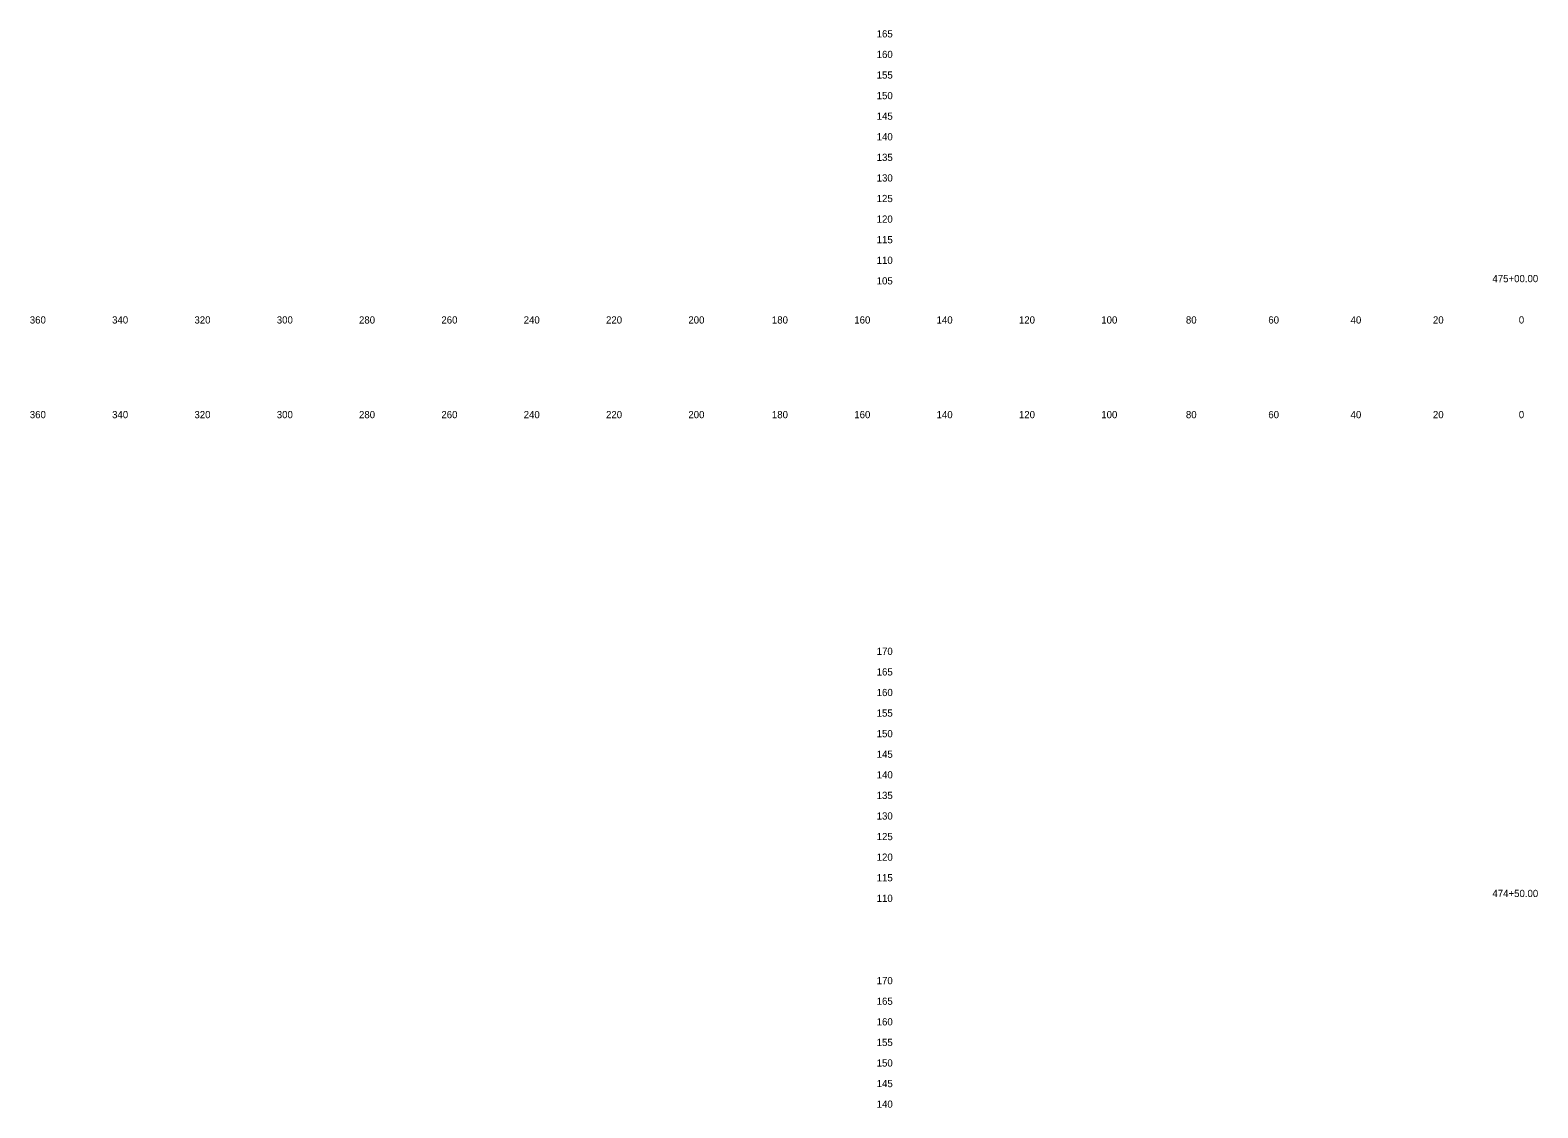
# Model space of a CAD drawing. Extents: x 21281 to 22024, y 6472 to 15198.
# Drawn here: x 21280.5 to 21646.7, y 11114.8 to 11376.6 of the extents above; entities that cross this region are included whole.
import ezdxf

# ---------------------------------------------------------------- set-up
doc = ezdxf.new("R2010")
doc.units = 0
for name, color, linetype in [('Draft_XS_Grid', 7, 'Continuous'), ('Draft_XS_Text', 7, 'Continuous'), ('SLOPE_STAKES_FILL', 7, 'Continuous')]:
    doc.layers.add(name, color=color, linetype=linetype)

msp = doc.modelspace()

# ---------------------------------------------------------------- texts
at = {"layer": 'Draft_XS_Grid'}
for s, p in [('  165  ', (21484.84, 11374.84)), ('  160  ', (21484.84, 11369.84)), ('  155  ', (21484.84, 11364.84)), ('  150  ', (21484.84, 11359.84)), ('  145  ', (21484.84, 11354.84)), ('  140  ', (21484.84, 11349.84)), ('  135  ', (21484.84, 11344.84)), ('  130  ', (21484.84, 11339.84)), ('  125  ', (21484.84, 11334.84)), ('  120  ', (21484.84, 11329.84)), ('  115  ', (21484.84, 11324.84)), ('  110  ', (21484.84, 11319.84)), ('  105  ', (21484.84, 11314.84)), ('  170  ', (21484.84, 11224.84)), ('  165  ', (21484.84, 11219.84)), ('  160  ', (21484.84, 11214.84)), ('  155  ', (21484.84, 11209.84)), ('  150  ', (21484.84, 11204.84)), ('  145  ', (21484.84, 11199.84)), ('  140  ', (21484.84, 11194.84)), ('  135  ', (21484.84, 11189.84)), ('  130  ', (21484.84, 11184.84)), ('  125  ', (21484.84, 11179.84)), ('  120  ', (21484.84, 11174.84)), ('  115  ', (21484.84, 11169.84)), ('  110  ', (21484.84, 11164.84)), ('  170  ', (21484.84, 11144.84)), ('  165  ', (21484.84, 11139.84)), ('  160  ', (21484.84, 11134.84)), ('  155  ', (21484.84, 11129.84)), ('  150  ', (21484.84, 11124.84)), ('  145  ', (21484.84, 11119.84)), ('  140  ', (21484.84, 11114.84))]:
    msp.add_text(s, height=1.75, dxfattribs=at).set_placement(p)
at = {"layer": 'Draft_XS_Text'}
for s, p in [('  360  ', (21279.14, 11305.34)), ('  340  ', (21299.13, 11305.34)), ('  320  ', (21319.13, 11305.34)), ('  300  ', (21339.13, 11305.34)), ('  280  ', (21359.1, 11305.34)), ('  260  ', (21379.11, 11305.34)), ('  240  ', (21399.1, 11305.34)), ('  220  ', (21419.1, 11305.34)), ('  200  ', (21439.1, 11305.34)), ('  180  ', (21459.39, 11305.34)), ('  160  ', (21479.4, 11305.34)), ('  140  ', (21499.39, 11305.34)), ('  120  ', (21519.39, 11305.34)), ('  100  ', (21539.39, 11305.34)), ('  80  ', (21559.95, 11305.34)), ('  60  ', (21579.97, 11305.34)), ('  40  ', (21599.95, 11305.34)), ('  20  ', (21619.95, 11305.34)), ('  0  ', (21640.81, 11305.34)), ('  0  ', (21640.81, 11305.34)), ('  360  ', (21279.14, 11282.34)), ('  340  ', (21299.13, 11282.34)), ('  320  ', (21319.13, 11282.34)), ('  300  ', (21339.13, 11282.34)), ('  280  ', (21359.1, 11282.34)), ('  260  ', (21379.11, 11282.34)), ('  240  ', (21399.1, 11282.34)), ('  220  ', (21419.1, 11282.34)), ('  200  ', (21439.1, 11282.34)), ('  180  ', (21459.39, 11282.34)), ('  160  ', (21479.4, 11282.34)), ('  140  ', (21499.39, 11282.34)), ('  120  ', (21519.39, 11282.34)), ('  100  ', (21539.39, 11282.34)), ('  80  ', (21559.95, 11282.34)), ('  60  ', (21579.97, 11282.34)), ('  40  ', (21599.95, 11282.34)), ('  20  ', (21619.95, 11282.34)), ('  0  ', (21640.81, 11282.34)), ('  0  ', (21640.81, 11282.34))]:
    msp.add_text(s, height=1.75, dxfattribs=at).set_placement(p)
at = {"layer": 'SLOPE_STAKES_FILL'}
for s, p in [('  475+00.00  ', (21634.4, 11315.38)), ('  474+50.00  ', (21634.4, 11166.03))]:
    msp.add_text(s, height=1.75, dxfattribs=at).set_placement(p)

doc.saveas('drawing.dxf')
